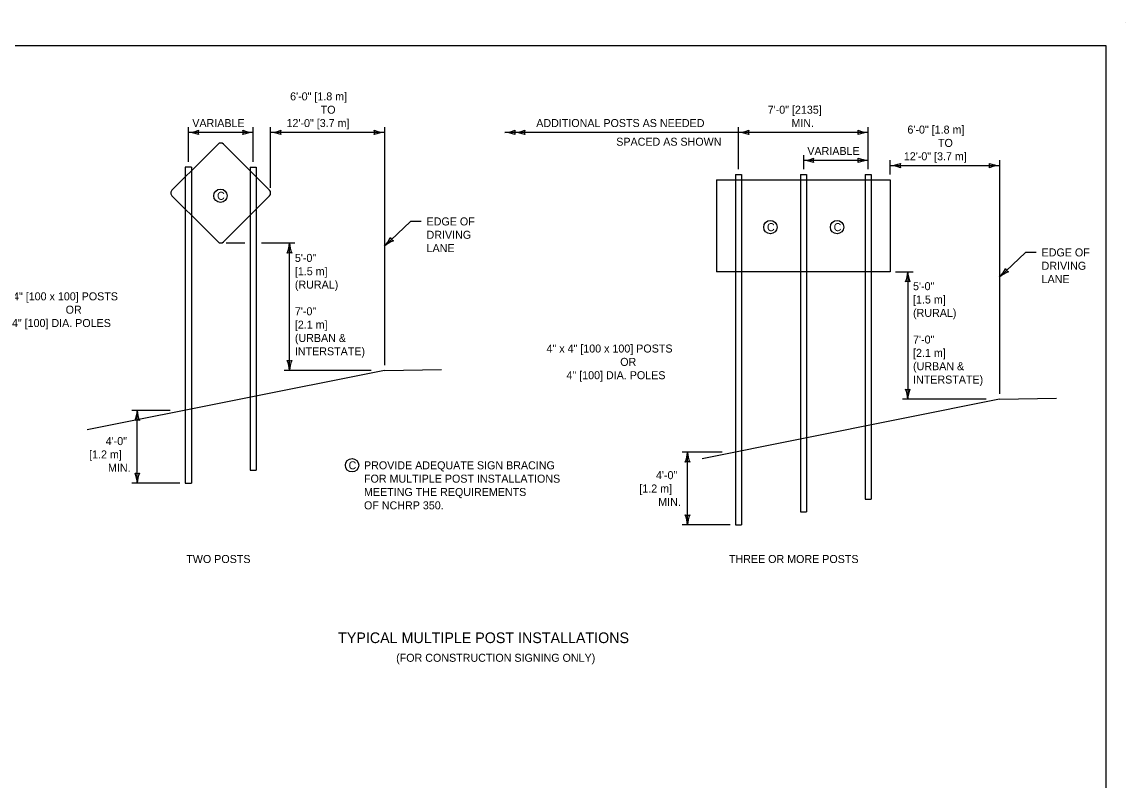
# Model space of a CAD drawing. Extents: x 49991.4 to 50021, y 49987.6 to 50011.4.
# Drawn here: x 50008.62 to 50016.9, y 49993.49 to 49999.18 of the extents above; entities that cross this region are included whole.
import ezdxf

# ---------------------------------------------------------------- set-up
doc = ezdxf.new("R2010")
doc.units = 0
for name, color, linetype in [('Level 1', 7, 'Continuous'), ('Level 2', 7, 'Continuous'), ('Level 3', 7, 'Continuous'), ('Level 4', 7, 'Continuous')]:
    doc.layers.add(name, color=color, linetype=linetype)

msp = doc.modelspace()

# ---------------------------------------------------------------- linework, layer by layer
at = {"layer": 'Level 1'}
for p, q in [((50016.9001, 49999.1756), (50016.9001, 49999.1756)), ((50010.0915, 49998.2603), (50009.8915, 49998.0605)), ((50010.1316, 49998.2603), (50010.1318, 49998.2604)), ((50010.3319, 49998.0601), (50010.1316, 49998.2603)), ((50009.846, 49998.088), (50009.846, 49996.265)), ((50009.8915, 49998.088), (50009.846, 49998.088)), ((50009.8915, 49998.088), (50009.8915, 49996.2741)), ((50010.3319, 49998.0885), (50010.3319, 49996.3622)), ((50010.3319, 49998.0885), (50010.3774, 49998.0885)), ((50010.3774, 49998.0885), (50010.3774, 49996.3713)), ((50013.9726, 49998.034), (50013.9726, 49995.9522)), ((50013.9726, 49998.034), (50014.0182, 49998.034)), ((50014.0182, 49998.034), (50014.0182, 49995.9613)), ((50014.4585, 49998.034), (50014.4585, 49996.0494)), ((50014.4585, 49998.034), (50014.5041, 49998.034)), ((50014.5041, 49998.034), (50014.5041, 49996.0585)), ((50014.9444, 49998.034), (50014.9444, 49996.1465)), ((50014.9444, 49998.034), (50014.9899, 49998.034)), ((50014.9899, 49998.034), (50014.9899, 49996.1556)), ((50009.846, 49998.015), (50009.7453, 49997.9144)), ((50010.4777, 49997.9144), (50010.3774, 49998.0146)), ((50013.83, 49997.994), (50013.83, 49997.304)), ((50013.83, 49997.994), (50013.9726, 49997.994)), ((50014.0182, 49997.994), (50014.4585, 49997.994)), ((50014.5041, 49997.994), (50014.9444, 49997.994)), ((50014.9899, 49997.994), (50015.1326, 49997.994)), ((50015.1326, 49997.994), (50015.1326, 49997.304)), ((50009.7453, 49997.9144), (50009.7455, 49997.9144)), ((50009.7455, 49997.8741), (50009.7453, 49997.8742)), ((50009.7453, 49997.8742), (50009.846, 49997.7736)), ((50010.3772, 49997.774), (50010.4775, 49997.8742)), ((50010.4775, 49997.8742), (50010.4777, 49997.8742)), ((50009.8915, 49997.7281), (50010.0888, 49997.5309)), ((50010.1342, 49997.5308), (50010.3319, 49997.7284)), ((50010.0888, 49997.5309), (50010.0916, 49997.5281)), ((50010.1318, 49997.5281), (50010.1342, 49997.5308)), ((50013.9726, 49997.304), (50013.83, 49997.304)), ((50014.4585, 49997.304), (50014.0182, 49997.304)), ((50014.9444, 49997.304), (50014.5041, 49997.304)), ((50015.1326, 49997.304), (50014.9899, 49997.304)), ((50011.3395, 49996.5636), (50009.1104, 49996.118)), ((50011.3395, 49996.5636), (50011.7682, 49996.5723)), ((50015.952, 49996.3479), (50013.7229, 49995.9023)), ((50015.952, 49996.3479), (50016.3807, 49996.3566))]:
    msp.add_line(p, q, dxfattribs=at)
msp.add_lwpolyline([(49999.3835, 49998.9992), (50016.7501, 49998.9992), (50016.7501, 49987.7988), (49999.3835, 49987.7988)], close=True, dxfattribs=at)
for centre, major_axis, start_param, end_param in [((50010.1117, 49998.2403), (0.0285, 0), 0.785398, 2.356194), ((50009.7657, 49997.8942), (-0.0285, 0), 5.497783, 7.068583), ((50010.4576, 49997.8943), (0.0285, 0), 5.497787, 7.068583), ((50010.1117, 49997.5482), (-0.0285, 0), 0.785406, 2.356194)]:
    msp.add_ellipse(centre, major_axis=major_axis, ratio=0.999996, start_param=start_param, end_param=end_param, dxfattribs=at)
at = {"layer": 'Level 2'}
for centre in [(50010.1096, 49997.8733), (50014.2335, 49997.6385), (50014.7336, 49997.6385), (50011.0962, 49995.853)]:
    msp.add_circle(centre, 0.05, dxfattribs=at)
at = {"layer": 'Level 3'}
for p, q in [((50009.8687, 49998.128), (50009.8687, 49998.3887)), ((50010.3546, 49998.1285), (50010.3546, 49998.3887)), ((50010.486, 49997.9343), (50010.486, 49998.3887)), ((50011.3395, 49998.3887), (50011.3395, 49996.6036)), ((50013.9954, 49998.074), (50013.9954, 49998.3887)), ((50014.9672, 49998.074), (50014.9672, 49998.3887)), ((50010.3546, 49998.3487), (50009.8687, 49998.3487)), ((50011.3395, 49998.3487), (50010.486, 49998.3487)), ((50013.9954, 49998.3487), (50012.2423, 49998.3487)), ((50014.9672, 49998.3487), (50013.9954, 49998.3487)), ((50014.4813, 49998.1791), (50014.4813, 49998.074)), ((50014.9672, 49998.1391), (50014.4813, 49998.1391)), ((50015.1326, 49998.034), (50015.1326, 49998.1397)), ((50015.952, 49998.1397), (50015.952, 49996.3879)), ((50015.1326, 49998.0997), (50015.952, 49998.0997)), ((50011.5354, 49997.6812), (50011.3395, 49997.4963)), ((50011.6154, 49997.6812), (50011.5354, 49997.6812)), ((50010.1517, 49997.5198), (50010.2919, 49997.5198)), ((50010.4174, 49997.5198), (50010.6677, 49997.5198)), ((50010.6277, 49996.5636), (50010.6277, 49997.5198)), ((50016.1478, 49997.4489), (50015.952, 49997.264)), ((50016.2278, 49997.4489), (50016.1478, 49997.4489)), ((50015.1726, 49997.304), (50015.3036, 49997.304)), ((50015.2636, 49997.304), (50015.2636, 49996.3479)), ((50011.2395, 49996.5636), (50010.5877, 49996.5636)), ((50015.852, 49996.3479), (50015.2236, 49996.3479)), ((50009.732, 49996.265), (50009.4458, 49996.265)), ((50009.4858, 49995.719), (50009.4858, 49996.265)), ((50013.8726, 49995.9522), (50013.5726, 49995.9522)), ((50013.6126, 49995.4061), (50013.6126, 49995.9522)), ((50009.806, 49995.719), (50009.4458, 49995.719)), ((50013.9326, 49995.4061), (50013.5726, 49995.4061))]:
    msp.add_line(p, q, dxfattribs=at)
for centre, radius, start, end in [((50009.8596, 49998.5709), 0.2223, 272.36048, 292.54399), ((50009.997, 49998.3487), 0.0548, 162.13882, 197.86118), ((50010.2264, 49998.3487), 0.0548, 342.13882, 17.86118), ((50010.3661, 49998.5814), 0.233, 247.92284, 267.17269), ((50010.4769, 49998.5708), 0.2223, 272.36048, 292.54399), ((50010.6142, 49998.3487), 0.0548, 162.13882, 197.86118), ((50011.2113, 49998.3487), 0.0548, 342.13882, 17.86118), ((50011.351, 49998.5814), 0.233, 247.92284, 267.17269), ((50012.2331, 49998.5709), 0.2223, 272.36048, 292.54399), ((50012.3065, 49998.5709), 0.2223, 272.36048, 292.54399), ((50012.3705, 49998.3487), 0.0548, 162.13882, 197.86118), ((50012.4439, 49998.3487), 0.0548, 162.13882, 197.86118), ((50013.9863, 49998.5709), 0.2223, 272.36048, 292.54399), ((50014.1236, 49998.3487), 0.0548, 162.13882, 197.86118), ((50014.8389, 49998.3487), 0.0548, 342.13882, 17.86118), ((50014.9787, 49998.5814), 0.233, 247.92284, 267.17269), ((50009.8573, 49998.116), 0.233, 67.92284, 87.17269), ((50010.3638, 49998.1266), 0.2223, 92.36048, 112.54399), ((50010.4745, 49998.116), 0.233, 67.92284, 87.17269), ((50011.3487, 49998.1265), 0.2223, 92.36048, 112.54399), ((50012.2308, 49998.116), 0.233, 67.92284, 87.17269), ((50012.3042, 49998.116), 0.233, 67.92284, 87.17269), ((50013.9839, 49998.116), 0.233, 67.92284, 87.17269), ((50014.9763, 49998.1266), 0.2223, 92.36048, 112.54399), ((50014.4721, 49998.3612), 0.2223, 272.36048, 292.54399), ((50014.4698, 49997.9064), 0.233, 67.92284, 87.17269), ((50014.6095, 49998.1391), 0.0548, 162.13882, 197.86118), ((50014.8389, 49998.1391), 0.0548, 342.13882, 17.86118), ((50014.9787, 49998.3718), 0.233, 247.92284, 267.17269), ((50014.9763, 49997.917), 0.2223, 92.36048, 112.54399), ((50015.1234, 49998.3218), 0.2223, 272.36048, 292.54399), ((50015.2608, 49998.0997), 0.0548, 162.13882, 197.86118), ((50015.8238, 49998.0997), 0.0548, 342.13882, 17.86118), ((50015.9635, 49998.3324), 0.233, 247.92284, 267.17269), ((50015.1211, 49997.867), 0.233, 67.92284, 87.17269), ((50015.9612, 49997.8776), 0.2223, 92.36048, 112.54399), ((50011.1804, 49997.6516), 0.2223, 315.7076, 335.89111), ((50011.4909, 49997.3192), 0.233, 111.26996, 130.51981), ((50011.4328, 49997.5843), 0.0548, 205.48594, 241.2083), ((50010.4056, 49997.5289), 0.2223, 337.45601, 357.63952), ((50010.4056, 49997.5289), 0.2223, 337.45601, 357.63952), ((50010.8604, 49997.5312), 0.233, 182.82731, 202.07716), ((50010.8604, 49997.5312), 0.233, 182.82731, 202.07716), ((50010.6277, 49997.3915), 0.0548, 72.13882, 107.86118), ((50010.6277, 49997.3915), 0.0548, 72.13882, 107.86118), ((50015.0415, 49997.3132), 0.2223, 337.45601, 357.63952), ((50015.0415, 49997.3132), 0.2223, 337.45601, 357.63952), ((50015.4963, 49997.3155), 0.233, 182.82731, 202.07716), ((50015.4963, 49997.3155), 0.233, 182.82731, 202.07716), ((50015.7929, 49997.4192), 0.2223, 315.7076, 335.89111), ((50016.1034, 49997.0869), 0.233, 111.26996, 130.51981), ((50016.0452, 49997.352), 0.0548, 205.48594, 241.2083), ((50015.2636, 49997.1758), 0.0548, 72.13882, 107.86118), ((50015.2636, 49997.1758), 0.0548, 72.13882, 107.86118), ((50010.6277, 49996.6918), 0.0548, 252.13882, 287.86118), ((50010.395, 49996.5521), 0.233, 2.82731, 22.07716), ((50010.8498, 49996.5544), 0.2223, 157.45601, 177.63952), ((50015.2636, 49996.4761), 0.0548, 252.13882, 287.86118), ((50015.0309, 49996.3364), 0.233, 2.82731, 22.07716), ((50015.4857, 49996.3387), 0.2223, 157.45601, 177.63952), ((50009.2531, 49996.2765), 0.233, 337.92284, 357.17269), ((50009.708, 49996.2742), 0.2223, 182.36048, 202.54399), ((50009.4858, 49996.1368), 0.0548, 72.13882, 107.86118), ((50013.3799, 49995.9637), 0.233, 337.92284, 357.17269), ((50013.6126, 49995.824), 0.0548, 72.13882, 107.86118), ((50013.8347, 49995.9614), 0.2223, 182.36048, 202.54399), ((50009.2637, 49995.7099), 0.2223, 2.36048, 22.54399), ((50009.4858, 49995.8472), 0.0548, 252.13882, 287.86118), ((50009.7186, 49995.7075), 0.233, 157.92284, 177.17269), ((50013.3904, 49995.3969), 0.2223, 2.36048, 22.54399), ((50013.6126, 49995.5343), 0.0548, 252.13882, 287.86118), ((50013.8453, 49995.3946), 0.233, 157.92284, 177.17269)]:
    msp.add_arc(centre, radius, start, end, dxfattribs=at)
at = {"layer": 'Level 4'}
for p, q in [((50009.846, 49998.015), (50009.8915, 49998.0605)), ((50010.3319, 49998.0601), (50010.3774, 49998.0146)), ((50013.9726, 49997.994), (50014.0182, 49997.994)), ((50014.4585, 49997.994), (50014.5041, 49997.994)), ((50014.9444, 49997.994), (50014.9899, 49997.994)), ((50009.8915, 49997.7281), (50009.846, 49997.7736)), ((50010.3774, 49997.7739), (50010.3319, 49997.7284)), ((50014.0182, 49997.304), (50013.9726, 49997.304)), ((50014.5041, 49997.304), (50014.4585, 49997.304)), ((50014.9899, 49997.304), (50014.9444, 49997.304)), ((50010.3319, 49996.3622), (50010.3319, 49995.8161)), ((50010.3774, 49996.3713), (50010.3774, 49995.8161)), ((50009.846, 49996.265), (50009.846, 49995.719)), ((50009.8915, 49996.2741), (50009.8915, 49995.719)), ((50014.9444, 49996.1465), (50014.9444, 49995.6003)), ((50014.9899, 49996.1556), (50014.9899, 49995.6003)), ((50014.4585, 49996.0494), (50014.4585, 49995.5033)), ((50014.5041, 49996.0585), (50014.5041, 49995.5033)), ((50014.0182, 49995.9613), (50014.0182, 49995.4061)), ((50013.9726, 49995.9522), (50013.9726, 49995.4061)), ((50010.3319, 49995.8161), (50010.3774, 49995.8161)), ((50009.846, 49995.719), (50009.8915, 49995.719)), ((50014.9444, 49995.6003), (50014.9899, 49995.6003)), ((50014.4585, 49995.5033), (50014.5041, 49995.5033)), ((50013.9726, 49995.4061), (50014.0182, 49995.4061))]:
    msp.add_line(p, q, dxfattribs=at)

# ---------------------------------------------------------------- texts
at = {"layer": 'Level 2'}
for s, height, p in [('6\'-0" [1.8 m]', 0.06, (50010.632, 49998.5887)), ('TO', 0.06, (50010.8611, 49998.4887)), ('7\'-0" [2135] ', 0.06, (50014.2137, 49998.4887)), ('VARIABLE', 0.06, (50009.8983, 49998.3887)), ('12\'-0" [3.7 m]', 0.06, (50010.6051, 49998.3887)), ('ADDITIONAL POSTS AS NEEDED', 0.06, (50012.4778, 49998.3887)), ('MIN.', 0.06, (50014.3915, 49998.3887)), ('6\'-0" [1.8 m]', 0.06, (50015.2615, 49998.3397)), ('SPACED AS SHOWN', 0.06, (50013.0778, 49998.2487)), ('TO', 0.06, (50015.4906, 49998.2397)), ('VARIABLE', 0.06, (50014.5108, 49998.1791)), ('12\'-0" [3.7 m]', 0.06, (50015.2346, 49998.1397)), ('C', 0.06, (50010.0841, 49997.8433)), ('EDGE OF', 0.06, (50011.6554, 49997.6512)), ('C', 0.06, (50014.2079, 49997.6085)), ('C', 0.06, (50014.7081, 49997.6085)), ('DRIVING', 0.06, (50011.6554, 49997.5512)), ('LANE', 0.06, (50011.6554, 49997.4512)), ('EDGE OF', 0.06, (50016.2678, 49997.4189)), ('5\'-0"', 0.06, (50010.6677, 49997.3776)), ('DRIVING', 0.06, (50016.2678, 49997.3189)), ('[1.5 m]', 0.06, (50010.6677, 49997.2776)), ('(RURAL)', 0.06, (50010.6677, 49997.1776)), ('5\'-0"', 0.06, (50015.3036, 49997.1659)), ('LANE', 0.06, (50016.2678, 49997.2189)), ('4" x 4" [100 x 100] POSTS', 0.06, (50008.3963, 49997.0896)), ('[1.5 m]', 0.06, (50015.3036, 49997.0659)), ('OR', 0.06, (50008.9487, 49996.9896)), ('7\'-0"', 0.06, (50010.6677, 49996.9776)), ('4" [100] DIA. POLES', 0.06, (50008.5458, 49996.8896)), ('(RURAL)', 0.06, (50015.3036, 49996.9659)), ('[2.1 m]', 0.06, (50010.6677, 49996.8776)), ('(URBAN &', 0.06, (50010.6677, 49996.7776)), ('7\'-0"', 0.06, (50015.3036, 49996.7659)), ('INTERSTATE)', 0.06, (50010.6677, 49996.6776)), ('4" x 4" [100 x 100] POSTS', 0.06, (50012.5552, 49996.6984)), ('[2.1 m]', 0.06, (50015.3036, 49996.6659)), ('OR', 0.06, (50013.1076, 49996.5984)), ('(URBAN &', 0.06, (50015.3036, 49996.5659)), ('4" [100] DIA. POLES', 0.06, (50012.7047, 49996.4984)), ('INTERSTATE)', 0.06, (50015.3036, 49996.4659)), ('4\'-0"', 0.06, (50009.2489, 49996.0047)), ('[1.2 m]', 0.06, (50009.1245, 49995.9047)), ('C', 0.06, (50011.0707, 49995.823)), ('PROVIDE ADEQUATE SIGN BRACING', 0.06, (50011.1862, 49995.823)), ('MIN.', 0.06, (50009.2662, 49995.8047)), ('4\'-0"', 0.06, (50013.3756, 49995.7492)), ('FOR MULTIPLE POST INSTALLATIONS', 0.06, (50011.1862, 49995.723)), ('[1.2 m]', 0.06, (50013.2512, 49995.6492)), ('MEETING THE REQUIREMENTS', 0.06, (50011.1862, 49995.623)), ('OF NCHRP 350.', 0.06, (50011.1862, 49995.523)), ('MIN.', 0.06, (50013.3929, 49995.5492)), ('TWO POSTS', 0.06, (50009.8534, 49995.1207)), ('THREE OR MORE POSTS', 0.06, (50013.9229, 49995.1207)), ('TYPICAL MULTIPLE POST INSTALLATIONS', 0.08, (50010.992, 49994.5202)), ('(FOR CONSTRUCTION SIGNING ONLY)', 0.06, (50011.4272, 49994.3802))]:
    msp.add_text(s, height=height, dxfattribs=at).set_placement(p)

doc.saveas('drawing.dxf')
